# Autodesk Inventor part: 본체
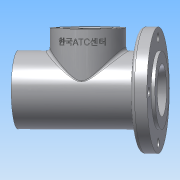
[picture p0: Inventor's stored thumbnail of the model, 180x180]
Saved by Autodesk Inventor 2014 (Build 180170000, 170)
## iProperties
Created: 2016-08
Part Number: 본체
Material: 알루미늄 6061
Document SubType Name: Modeling
Designer: 703
Density: 2.71 g/cm^3
Appearance: 알루미늄 - 평지
Mass: 767.644 g
Surface Area: 626.519 cm^2
Volume: 283.264 cm^3
Author: 703
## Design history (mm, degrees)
sketch "스케치1"
  geometry: C1 r 31 at (0, 0); 1 further point
  constraints: 1 centre point, 1 coincident
  dimensions: "d0" = 62 diameter of C1
extrude "돌출1" new body sketch "스케치1" stored distance "d1" = 99; taper "d2" = 0 deg
node "작업 평면1"
sketch "스케치2"
  geometry: L1 (31, 49.5)-(-31, 49.5) reference; C1 r 30 at (0, -6.5); 1 further point
  constraints: 1 centre point, 1 vertical alignment
  dimensions: "d4" = 56 distance from line of L1 C1.centre; "d5" = 60 diameter of C1
extrude "돌출2" join sketch "스케치2" stored distance "d6" = 102; taper "d7" = 0 deg
sketch "스케치3"
  geometry: C1 r 31 at (0, 0) reference; C2 r 50 at (0, 0)
  constraints: 1 centre point, 1 coincident
  dimensions: "d8" = 100 diameter of C2
extrude "돌출3" join sketch "스케치3" distance "d9" = 13; taper "d10" = 0 deg
node "작업 평면2"
node "작업 평면4"
sketch "스케치14"
  geometry: C1 r 26 at (0, 0); 1 further point
  constraints: 1 centre point, 1 coincident
  dimensions: "d37" = 52 diameter of C1
extrude "돌출9" cut sketch "스케치14" stored distance "d38" = 38; taper "d39" = 0 deg
sketch "스케치16"
  geometry: C1 r 30 at (0, 0) reference; C2 r 19 at (0, 0); 1 further point
  constraints: 1 centre point, 1 coincident
  dimensions: "d49" = 38 diameter of C2
extrude "돌출10" cut sketch "스케치16" stored distance "d50" = 38; taper "d51" = 0 deg
sketch "스케치17" dims "d52" = 48
  geometry: C1 r 19 at (0, 0) reference; C2 r 30 at (0, 0) reference; 3 further points
  constraints: 2 horizontal alignment, 1 coincident, 2 other
hole "구멍1" sketch "스케치17" at (-24, 0) diameter "d53" = 3.242; stored, may be unused: countersink angle "d57" = 90 deg, drill point angle "d59" = 118 deg; dims "d54" = 8, "d55" = 4, "d56" = 2, "d58" = 10
sketch "스케치19"
  geometry: C1 r 50 at (0, 0) reference; C2 r 31 at (0, 0)
  constraints: 1 centre point, 1 coincident
  dimensions: "d76" = 62 diameter of C2
extrude "돌출11" join sketch "스케치19" distance "d77" = 3; taper "d78" = 0 deg
node "작업 평면6"
sketch "스케치23"
  geometry: C1 r 16 at (0, 0); 1 further point
  constraints: 1 centre point, 1 coincident
  dimensions: "d87" = 32 diameter of C1
sketch "스케치24"
  geometry: C1 r 31 at (0, 0) reference; C2 r 21 at (0, 0)
  constraints: 1 centre point, 1 coincident
  dimensions: "d88" = 42 diameter of C2
feature "로프트3" sketch "스케치23", "스케치24" dims "d89" = 0, "d90" = 90 deg, "d91" = 0, "d92" = 90 deg
sketch "스케치25"
  geometry: L1 (0, 57.5)-(0, -57.5); L2 (-16, -51.5)-(16, -51.5) reference; L3 (12.5, -51.5)-(12.5, -44.2); L4 (12.5, -44.2)-(10, -44.2); L5 (10, -44.2)-(10, -41.5); L6 (10, -41.5)-(16.5, -41.5); L7 (16.5, -41.5)-(16.5, -36.5); L8 (16.5, -36.5)-(17.5, -36.5); L9 (17.5, -36.5)-(17.5, -25.5); L10 (-26, -25.5)-(26, -25.5) reference; L11 (21, -65.5)-(-21, -65.5) reference; L12 (17.5, -25.5)-(0, -25.5); L13 (0, -25.5)-(0, -51.5); L14 (12.5, -51.5)-(0, -51.5); 2 further points
  constraints: 22 end point, 5 parallel, 3 midpoint, 2 perpendicular, 2 point on line, 1 coincident, 1 collinear, 1 vertical
  dimensions: "d93" = 115 distance of L1.start L1.end; "d94" = 35 diameter of L9 L1; "d95" = 33 diameter of L7 L1; "d96" = 20 diameter of L5 L1; "d98" = 7.3 distance of L3.start L3.end; "d99" = 2.7 distance of L4.end L5.end; "d102" = 5 distance of L6.end L7.end; "d159" = 25 diameter of L3 L1
revolve "회전3" sketch "스케치25" stored, may be unused: angle "d103" = 90 deg
fillet "모깎기1" dims "d104" = 3
chamfer "모따기2" distance "d109" = 0.7; stored, may be unused: second distance "d110" = 2, angle "d111" = 30 deg
fillet "모깎기3" dims "d112" = 0.3
fillet "모깎기5" dims "d114" = 3
fillet "모깎기7" dims "d116" = 3
fillet "모깎기8" dims "d117" = 0.3
sketch "스케치27"
  geometry: L1 (0, 57.5)-(0, -57.5); L2 (21.138, 12.5)-(-23, 12.5) reference; L3 (17.5, 12.5)-(17.5, 23.5); L4 (17.5, 23.5)-(18.5, 23.5); L5 (18.5, 23.5)-(18.5, 25.25); L6 (18.5, 25.25)-(17.5, 25.25); L7 (17.5, 25.25)-(17.5, 28.5); L8 (17.5, 28.5)-(20, 28.5); L9 (20, 28.5)-(20, 37.5); L10 (20, 37.5)-(24, 37.5); L11 (24, 37.5)-(24, 40.5); L12 (24, 40.5)-(0, 40.5); L13 (0, 40.5)-(0, 12.5); L14 (0, 12.5)-(17.5, 12.5); L15 (31, 49.5)-(-31, 49.5) reference; 2 further points
  constraints: 26 end point, 6 parallel, 4 point on line, 3 perpendicular, 2 collinear, 1 coincident, 1 midpoint, 1 vertical, 1 vertical alignment
  dimensions: "d118" = 115 distance of L1.start L1.end; "d119" = 12 distance between parallel lines of L10 L15; "d120" = 21 distance between parallel lines of L8 L15; "d121" = 26 distance between parallel lines of L15 L4; "d123" = 35 diameter of L3 L1; "d124" = 1.75 distance of L4.end L5.end; "d125" = 37 diameter of L5 L1; "d126" = 3 distance of L10.end L11.end; "d127" = 48 diameter of L11 L1; "d128" = 40 diameter of L9 L1
revolve "회전4" sketch "스케치27" stored, may be unused: angle "d129" = 90 deg
sketch "스케치28" dims "d130" = 83
  geometry: C1 r 50 at (0, 0) reference; C2 r 31 at (0, 0) reference; C3 r 4 at (0, 41.5); 2 further points
  constraints: 2 coincident, 2 vertical alignment, 1 centre point, 2 other
  dimensions: "d132" = 8 diameter of C3
extrude "돌출12" cut sketch "스케치28" stored distance "d133" = 3; taper "d134" = 0 deg
chamfer "모따기3" distance "d138" = 1; stored, may be unused: second distance "d139" = 2, angle "d140" = 30 deg
fillet "모깎기9" dims "d141" = 3
node "작업 평면7"
sketch "스케치29"
  geometry: L1 (-18, 56)-(-80, 56) reference; L2 (0, 30)-(0, -30) reference; 2 further points
  constraints: 1 other
  dimensions: "d142" = 56 distance from line of L1 point (-10, 0); "d143" = 10 distance from line of L2 point (-10, 0)
feature "엠보싱1" sketch "스케치29" dims "d0" = 62, "d144" = 0.5, "d145" = 0
fillet "모깎기10" dims "d146" = 3
node "작업 평면8"
hole "구멍2" diameter "d151" = 40.376; stored, may be unused: countersink angle "d155" = 90 deg, drill point angle "d157" = 0 deg; dims "d149" = 10, "d150" = 10, "d152" = 42, "d153" = 4, "d154" = 2, "d156" = 9
fillet "모깎기11" dims "d158" = 0.3
node "솔리드1"
pattern_circular "원형 패턴1" dims angle "d61" = 360 deg
pattern_circular "원형 패턴2" dims angle "d136" = 360 deg
other parameters: "d3" = 49, "d15" = -14, "d36" = -56, "d86" = -14, "d147" = -9
